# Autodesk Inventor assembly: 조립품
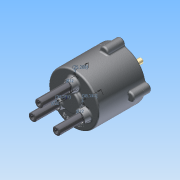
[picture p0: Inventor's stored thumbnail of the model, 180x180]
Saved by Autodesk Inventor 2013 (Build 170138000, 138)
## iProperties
Created: 2014-12
Part Number: 조립품
Document SubType Name: Assembly
Designer: Administrator
Mass: 2160.23 g
Surface Area: 1801.16 cm^2
Volume: 438.522 cm^3
Density: 4.92618 g/cm^3
Author: Administrator
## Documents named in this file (14)
- C:\Users\CANON\Desktop\Inventor1급-강정희\조립품.iam
- C:\Users\CANON\Desktop\Inventor1급-강정희\몸체.ipt
- C:\Users\CANON\Desktop\Inventor1급-강정희\판캠.ipt
- C:\Users\CANON\Desktop\Inventor1급-강정희\베어링 NA 4900.ipt
- C:\Users\CANON\Desktop\Inventor1급-강정희\메인 축.ipt
- C:\Users\CANON\Desktop\Inventor1급-강정희\멈춤링 10 x 1.ipt
- C:\Users\CANON\Desktop\Inventor1급-강정희\멈춤링 22 x 1.2.ipt
- C:\Users\CANON\Desktop\Inventor1급-강정희\슬라이드 축.ipt
- C:\Users\CANON\Desktop\Inventor1급-강정희\커버.ipt
- C:\Users\CANON\Desktop\Inventor1급-강정희\오일실.ipt
- C:\Users\CANON\Desktop\Inventor1급-강정희\M5x0.5x20.ipt
- C:\Users\CANON\Desktop\Inventor1급-강정희\가변스프링 1.ipt
- C:\Users\CANON\Desktop\Inventor1급-강정희\가변스프링2.ipt
- C:\Users\CANON\Desktop\Inventor1급-강정희\가변스프링3.ipt
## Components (7 placed, 4 different names)
1. 가변스프링 1:1 — Mate:15, Mate:22, Mate:25
2. 가변스프링2:1 — Mate:16, Mate:23, Mate:27
3. 가변스프링3:1 — Mate:17, Mate:21, Mate:26
4. M5x0.5x20:1 — Insert:7
5. M5x0.5x20:2
6. M5x0.5x20:3
7. M5x0.5x20:4
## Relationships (10: Mate 9, Insert 1)
- Insert:7: M5x0.5x20:1
- Mate:15: 가변스프링 1:1
- Mate:16: 가변스프링2:1
- Mate:17: 가변스프링3:1
- Mate:21: 가변스프링3:1
- Mate:22: 가변스프링 1:1
- Mate:23: 가변스프링2:1
- Mate:25: 가변스프링 1:1
- Mate:26: 가변스프링3:1
- Mate:27: 가변스프링2:1
